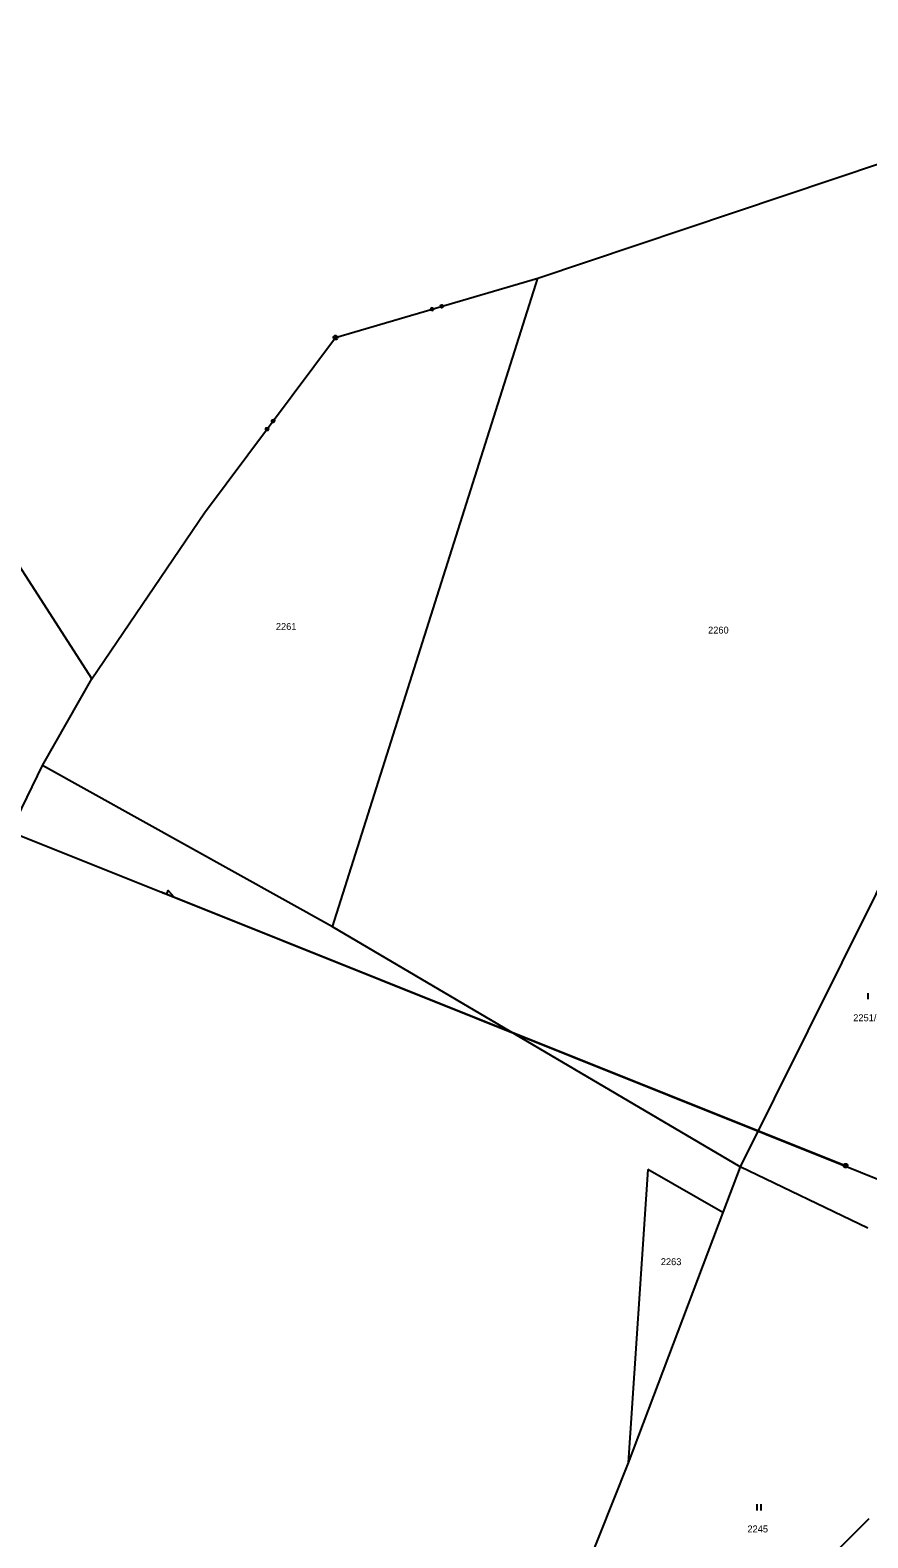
# Model space of a CAD drawing. Extents: x -747792 to -745414, y -1093712 to -1091463.
# Drawn here: x -746474.4 to -746371.5, y -1092533.3 to -1092348.3 of the extents above; entities that cross this region are included whole.
import ezdxf

# ---------------------------------------------------------------- set-up
doc = ezdxf.new("R2010")
doc.units = 0
for name, color, linetype in [('Pracovní_bod JDTM STC_VC', 7, 'Continuous'), ('Pracovní_bod JDTM STC_VC - číslo', 7, 'Continuous'), ('Pracovní_bod NN - výška', 7, 'Continuous'), ('Pracovní_bod polohopisu', 7, 'Continuous'), ('Pracovní_bod polohopisu - číslo', 7, 'Continuous'), ('Pracovní_bod VN - výška', 7, 'Continuous')]:
    doc.layers.add(name, color=color, linetype=linetype)

msp = doc.modelspace()

# ---------------------------------------------------------------- linework, layer by layer
at = {"layer": 'Pracovní_bod JDTM STC_VC - číslo'}
for points in [[(-746371.54, -1092466.48), (-746371.54, -1092467.23)], [(-746385.14, -1092529.2), (-746385.14, -1092529.95)], [(-746384.64, -1092529.95), (-746384.64, -1092529.2)]]:
    msp.add_lwpolyline(points, dxfattribs=at)
at = {"layer": 'Pracovní_bod NN - výška'}
for points in [[(-746412.03, -1092378.75), (-746321.34, -1092348.34)], [(-746437.24, -1092458.36), (-746412.03, -1092378.75)], [(-746436.87, -1092386.06), (-746412.03, -1092378.75)], [(-746425.01, -1092382.4), (-746424.89, -1092382.47), (-746424.85, -1092382.6), (-746424.92, -1092382.71), (-746425.05, -1092382.75), (-746425.16, -1092382.69), (-746425.2, -1092382.56), (-746425.14, -1092382.44), (-746425.01, -1092382.4), (-746425.01, -1092382.42), (-746425.12, -1092382.46), (-746425.15, -1092382.51), (-746424.96, -1092382.45), (-746424.91, -1092382.48), (-746425.18, -1092382.56), (-746425.17, -1092382.59), (-746424.9, -1092382.52), (-746424.89, -1092382.55), (-746425.15, -1092382.63), (-746425.14, -1092382.67), (-746424.87, -1092382.59), (-746424.9, -1092382.64), (-746425.09, -1092382.7), (-746425.04, -1092382.73), (-746424.93, -1092382.69)], [(-746423.81, -1092382.05), (-746423.69, -1092382.11), (-746423.65, -1092382.24), (-746423.72, -1092382.36), (-746423.85, -1092382.4), (-746423.96, -1092382.34), (-746424, -1092382.21), (-746423.94, -1092382.09), (-746423.81, -1092382.05), (-746423.82, -1092382.07), (-746423.93, -1092382.11), (-746423.96, -1092382.16), (-746423.77, -1092382.1), (-746423.72, -1092382.13), (-746423.99, -1092382.21), (-746423.98, -1092382.24), (-746423.71, -1092382.17), (-746423.7, -1092382.2), (-746423.96, -1092382.28), (-746423.95, -1092382.32), (-746423.68, -1092382.24), (-746423.71, -1092382.29), (-746423.9, -1092382.35), (-746423.85, -1092382.38), (-746423.74, -1092382.34)], [(-746452.96, -1092407.55), (-746436.87, -1092386.06)], [(-746445.36, -1092397.14), (-746445.23, -1092397.12), (-746445.12, -1092397.2), (-746445.1, -1092397.33), (-746445.18, -1092397.44), (-746445.32, -1092397.46), (-746445.43, -1092397.38), (-746445.44, -1092397.25), (-746445.36, -1092397.14), (-746445.35, -1092397.15), (-746445.42, -1092397.25), (-746445.41, -1092397.31), (-746445.29, -1092397.15), (-746445.24, -1092397.14), (-746445.41, -1092397.36), (-746445.37, -1092397.39), (-746445.21, -1092397.16), (-746445.17, -1092397.19), (-746445.34, -1092397.41), (-746445.31, -1092397.43), (-746445.14, -1092397.21), (-746445.13, -1092397.27), (-746445.25, -1092397.43), (-746445.2, -1092397.42), (-746445.13, -1092397.32)], [(-746444.61, -1092396.14), (-746444.48, -1092396.12), (-746444.37, -1092396.2), (-746444.35, -1092396.33), (-746444.44, -1092396.44), (-746444.57, -1092396.46), (-746444.68, -1092396.38), (-746444.7, -1092396.24), (-746444.61, -1092396.14), (-746444.61, -1092396.16), (-746444.68, -1092396.26), (-746444.67, -1092396.31), (-746444.55, -1092396.15), (-746444.5, -1092396.14), (-746444.66, -1092396.37), (-746444.63, -1092396.39), (-746444.46, -1092396.17), (-746444.43, -1092396.19), (-746444.6, -1092396.42), (-746444.57, -1092396.44), (-746444.4, -1092396.22), (-746444.39, -1092396.27), (-746444.51, -1092396.43), (-746444.46, -1092396.42), (-746444.38, -1092396.33)], [(-746483.56, -1092401.9), (-746466.77, -1092427.92)], [(-746466.77, -1092427.92), (-746452.96, -1092407.55)], [(-746472.83, -1092438.56), (-746466.77, -1092427.92)], [(-746362.25, -1092437.65), (-746387.21, -1092487.8)], [(-746494.41, -1092482.98), (-746472.83, -1092438.56)], [(-746437.24, -1092458.36), (-746472.83, -1092438.56)], [(-746387.21, -1092487.8), (-746437.24, -1092458.36)], [(-746398.54, -1092488.13), (-746400.96, -1092524.11)], [(-746389.32, -1092493.38), (-746398.54, -1092488.13)], [(-746387.21, -1092487.8), (-746389.32, -1092493.38)], [(-746371.51, -1092495.32), (-746387.21, -1092487.8)], [(-746389.32, -1092493.38), (-746400.96, -1092524.11)], [(-746400.96, -1092524.11), (-746409.92, -1092546.62)]]:
    msp.add_lwpolyline(points, dxfattribs=at)
at = {"layer": 'Pracovní_bod polohopisu'}
msp.add_lwpolyline([(-746375.8, -1092535.36), (-746371.38, -1092530.96)], dxfattribs=at)
at = {"layer": 'Pracovní_bod polohopisu - číslo'}
for points in [[(-746539.05, -1092421.79), (-746374.26, -1092487.66), (-746458.28, -1092454.08)], [(-746458.05, -1092454.17), (-746457.59, -1092454.36), (-746457.4, -1092453.89), (-746456.66, -1092454.73), (-746455.26, -1092455.28)], [(-746455.03, -1092455.38), (-746266.15, -1092531.03), (-746362.22, -1092492.55)], [(-746374.33, -1092487.42), (-746374.18, -1092487.42), (-746374.05, -1092487.51), (-746374.01, -1092487.65), (-746374.05, -1092487.8), (-746374.18, -1092487.89), (-746374.33, -1092487.89), (-746374.46, -1092487.8), (-746374.51, -1092487.65), (-746374.46, -1092487.51), (-746374.33, -1092487.42), (-746374.32, -1092487.44), (-746374.2, -1092487.44), (-746374.12, -1092487.48), (-746374.4, -1092487.48), (-746374.44, -1092487.52), (-746374.08, -1092487.52), (-746374.08, -1092487.56), (-746374.44, -1092487.56), (-746374.46, -1092487.6), (-746374.06, -1092487.6), (-746374.04, -1092487.64), (-746374.48, -1092487.64), (-746374.48, -1092487.68), (-746374.04, -1092487.68), (-746374.05, -1092487.72), (-746374.46, -1092487.72), (-746374.46, -1092487.76), (-746374.05, -1092487.76), (-746374.08, -1092487.8), (-746374.44, -1092487.8), (-746374.4, -1092487.84), (-746374.11, -1092487.84), (-746374.17, -1092487.88), (-746374.34, -1092487.88)]]:
    msp.add_lwpolyline(points, dxfattribs=at)
at = {"layer": 'Pracovní_bod VN - výška'}
msp.add_lwpolyline([(-746436.79, -1092385.82), (-746436.67, -1092385.92), (-746436.62, -1092386.06), (-746436.67, -1092386.21), (-746436.79, -1092386.3), (-746436.95, -1092386.3), (-746437.07, -1092386.21), (-746437.12, -1092386.06), (-746437.07, -1092385.92), (-746436.95, -1092385.82)], close=True, dxfattribs=at)
msp.add_lwpolyline([(-746436.9, -1092386.06), (-746436.84, -1092386.06)], dxfattribs=at)

# ---------------------------------------------------------------- texts
at = {"layer": 'Pracovní_bod JDTM STC_VC'}
for s, p in [('2261', (-746444.19, -1092421.93)), ('2260', (-746391.14, -1092422.37)), ('2251/3', (-746373.32, -1092469.93)), ('2263', (-746396.94, -1092499.86)), ('2245', (-746386.31, -1092532.65))]:
    msp.add_text(s, height=0.85, dxfattribs=at).set_placement(p)

doc.saveas('drawing.dxf')
